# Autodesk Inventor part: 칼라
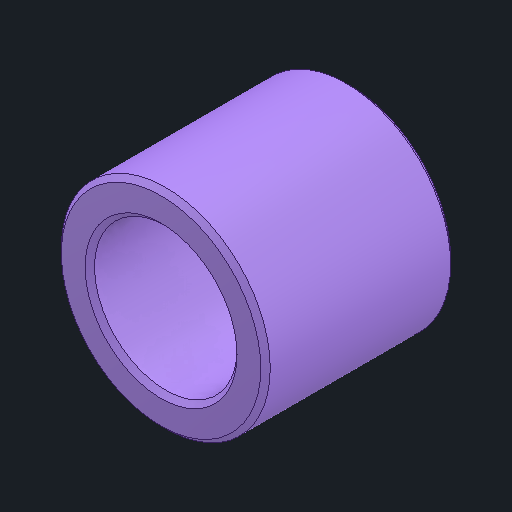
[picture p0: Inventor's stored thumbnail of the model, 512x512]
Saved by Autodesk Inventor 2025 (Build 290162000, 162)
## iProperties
Created: 2025-08
Part Number: 칼라
Material: 스테인리스강
Document SubType Name: Modeling
Designer: infra002
Density: 8.08 g/cm^3
Appearance: 기본값
Author: jhkim
Sending System: Autodesk Inventor 2026
Preprocessor: ST-DEVELOPER v20.1
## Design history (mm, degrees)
feature "솔리드1"
node "솔리드2"
